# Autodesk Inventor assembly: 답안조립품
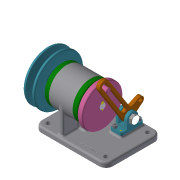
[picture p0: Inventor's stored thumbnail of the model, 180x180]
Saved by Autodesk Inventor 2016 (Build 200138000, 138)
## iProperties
Created: 2019-09
Part Number: 답안조립품
Material: 일반
Document SubType Name: Assembly
Designer: 605-11
Mass: 1417.67 g
Surface Area: 1426.65 cm^2
Volume: 427.118 cm^3
Density: 3.31915 g/cm^3
Author: 605-11
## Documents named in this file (19)
- C:\Users\605-11\Desktop\390904V1022\답안조립품.iam
- C:\Users\605-11\Desktop\390904V1022\본체.ipt
- C:\Users\605-11\Desktop\390904V1022\베어링 6004.ipt
- C:\Users\605-11\Desktop\390904V1022\볼트 M4.ipt
- C:\Users\605-11\Desktop\390904V1022\오일 실 17 30 5.ipt
- C:\Users\605-11\Desktop\390904V1022\커버.ipt
- C:\Users\605-11\Desktop\390904V1022\V-벨트풀리.ipt
- C:\Users\605-11\Desktop\390904V1022\너트 M10x1.ipt
- C:\Users\605-11\Desktop\390904V1022\축.ipt
- C:\Users\605-11\Desktop\390904V1022\키 4 x 4 x 8.ipt
- C:\Users\605-11\Desktop\390904V1022\키 5 x 5 x 12.ipt
- C:\Users\605-11\Desktop\390904V1022\멈춤나사 M3x5.ipt
- C:\Users\605-11\Desktop\390904V1022\너트 M8.ipt
- C:\Users\605-11\Desktop\390904V1022\와셔 8x15.5.ipt
- C:\Users\605-11\Desktop\390904V1022\크랭크.ipt
- C:\Users\605-11\Desktop\390904V1022\힌지 축.ipt
- C:\Users\605-11\Desktop\390904V1022\힌지.ipt
- C:\Users\605-11\Desktop\390904V1022\핀 3 x 8.ipt
- C:\Users\605-11\Desktop\390904V1022\돌림판.ipt
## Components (3 placed, 2 different names)
1. V-벨트풀리:1
2. 핀 3 x 8:1 — 플러쉬:1
3. 핀 3 x 8:2 — 플러쉬:2
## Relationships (2: Flush 2)
- 플러쉬:1 [Flush]: 핀 3 x 8:1
- 플러쉬:2 [Flush]: 핀 3 x 8:2
